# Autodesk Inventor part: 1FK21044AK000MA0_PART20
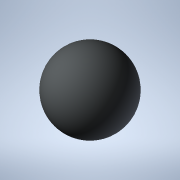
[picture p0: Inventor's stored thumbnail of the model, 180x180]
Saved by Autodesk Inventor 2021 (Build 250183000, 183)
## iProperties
Created: 2025-04
Part Number: 1FK21044AK000MA0_PART20
Material: Generic
Catalog Web Link: www.3dfindit.com
Description: -Servo synchronous motor
Document SubType Name: Modeling
Designer: psAdmin
Mass: 0.137258 g
Surface Area: 1.2868 cm^2
Volume: 0.137258 cm^3
Density: 1 g/cm^3
Appearance: PSOLRGB-212-217-219
Category: PARTsolutions
Title: 1FK21044AK000MA0_PART20
Author: Cadenas PARTsolutions
Comments: Servo synchronous motor
Sending System: PARTsolutions
Preprocessor: ST-DEVELOPER v19.3
PSOL_IDENT_0: {$CADENAS_DATA/23d-libs/siemens_ag/_cat_/87/f4/1fk21044ak000ma0.prj},216 {VTYP=3D},{NB=1FK21044AK000
PSOL_IDENT_1: MA0_PART20},{LINA=1FK21044AK000MA0_PART20},{NN=1FK21044AK000MA0_PART20},{NOPRJ=TRUE},{DATE=19.08.202
PSOL_IDENT_2: 5 14:00:48},{GEOMDATE=30.07.2025 02:00:50},{VERSION=},{LINEID=10},{WBVAR=},{WBNUMERIC=}  {NB=1FK2104
PSOL_IDENT_3: 4AK000MA0_PART20},{LINA=1FK21044AK000MA0_PART20},{KT=DUMMY},{PREVIEW=../../../_pool_/cb/72/p_d211_xx
PSOL_IDENT_4: _00434j.png},{DESCSHORT=SIMOTICS S-1FK2 HD, SINAMICS S210 3AC 400V-480V, 0.95 Nm, 6000 rpm},{DESCLON
PSOL_IDENT_5: G=SIMOTICS S-1FK2 HD servo motor M0=1.27 Nm; PN = 0.6 kW at nN=6000 rpm (380-480 V); PN = 0.4 kW at
PSOL_IDENT_6: nN=3000 rpm (200-240 V); degree of protection IP64; cylindrical shaft D19x40mm; absolute encoder 22-
PSOL_IDENT_7: bit + 12-bit multiturn (encoder AM22DQC); with OCC interface; plug size M17, rotatable; SIMOTICS S-1
PSOL_IDENT_8: FK2 servomotorfor a wide range of uses in industrial environments. SIMOTICS S‑1FK2 servomotors are c
PSOL_IDENT_9: ompact synchronous motors with a high dynamic performance that set themselves apart as a result of t
PSOL_IDENT_10: heir high power density, degree of protection and overload capability. The motors are available in t
PSOL_IDENT_11: wo variants: as High Dynamic variant (highest dynamic performance as a result of the low intrinsic m
PSOL_IDENT_12: oment of inertia for applications demanding a high dynamic performance with low moved masses) - and
PSOL_IDENT_13: as Compact variant (precise and stable closed-loop control for medium up to large moved masses as a
PSOL_IDENT_14: result of a medium intrinsic moment of inertia). SIMOTICSS‑1FK2 servomotors fully exploit their stre
PSOL_IDENT_15: ngths in a system with the SINAMICSS210 frequency converter and simple connection using the one cabl
PSOL_IDENT_16: e connection (OCC). Advantages include the short control and positioning times, fast and precise cor
PSOL_IDENT_17: rection of disturbing quantities as well as stable control with a high dynamic performance. The serv
PSOL_IDENT_18: o motors can be configured to address a wide range of requirements. For example with and without hol
PSOL_IDENT_19: ding brake, IP64 or IP65 degree of protection, singleturn or multiturn absolute encoders - to name j
PSOL_IDENT_20: ust a few. Further, the servomotors are available in different shaft heights extending from 20 to 10
PSOL_IDENT_21: 0. A shaft sealing ring is available to achieve an IP65 degree of protection and for subsequent moun
PSOL_IDENT_22: ting at the motor or as spare part. SIMOTICS - the optimum motor for each and every motion control a
PSOL_IDENT_23: pplication.},{INTNO=195125056312},{SUPPLIERALTNO=1FK2104-4AK00-0MA0},{MANUID=1FK21044AK000MA0},{MANU
PSOL_IDENT_24: NAME=Siemens},{MANUTYPEDESC=Synchronous motor 1FK2-HD 1,27 Nm},{AAU732=SIMOTICS},{AAO057=S-1FK2},{AA
PSOL_IDENT_25: U734=SIMOTICS S-1FK2 HD servo motor M0=1.27 Nm; PN = 0.6 kW at nN=6000 rpm (380-480 V); PN = 0.4 kW
PSOL_IDENT_26: at nN=3000 rpm (200-240 V); degree of protection IP64; cylindrical shaft D19x40mm; absolute encoder
PSOL_IDENT_27: 22-bit + 12-bit multiturn (encoder AM22DQC); with OCC interface; plug size M17, rotatable;},{AAW338=
PSOL_IDENT_28: Synchronous motor 1FK2-HD 1,27 Nm},{AAO742=SIMOTICS},{AAO663=4042948690994},{NOCUPEROU=1},{PRICEQUAN
PSOL_IDENT_29: TITY=1},{QUANTITYMIN=1},{QUANTITYINT=1},{CTN=85015100},{COO=DE},{AAO676=1FK2104-4AK00-0MA0},{AAO677=
PSOL_IDENT_30: Siemens AG},{ORDERUNIT=C62},{CONTENTUNIT=C62}
NB: 1FK21044AK000MA0_PART20
NT: Servo synchronous motor
NBSYN: $MANUID._PART20
LINA: 1FK21044AK000MA0_PART20
CATALOG: SIEMENS
PREVIEW: ../../../_pool_/cb/72/p_d211_xx_00434j.png
DESCSHORT: SIMOTICS S-1FK2 HD, SINAMICS S210 3AC 400V-480V, 0.95 Nm, 6000 rpm
DESCLONG: SIMOTICS S-1FK2 HD servo motor M0=1.27 Nm; PN = 0.6 kW at nN=6000 rpm (380-480 V); PN = 0.4 kW at nN=3000 rpm (200-240 V); degree of protection IP64; cylindrica
INTNO: 195125056312
SUPPLIERALTNO: 1FK2104-4AK00-0MA0
MANUID: 1FK21044AK000MA0
MANUNAME: Siemens
MANUTYPEDESC: Synchronous motor 1FK2-HD 1,27 Nm
AAU732: SIMOTICS
AAO057: S-1FK2
AAU734: SIMOTICS S-1FK2 HD servo motor M0=1.27 Nm; PN = 0.6 kW at nN=6000 rpm (380-480 V); PN = 0.4 kW at nN=3000 rpm (200-240 V); degree of protection IP64; cylindrica
AAW338: Synchronous motor 1FK2-HD 1,27 Nm
AAO742: SIMOTICS
AAO663: 4042948690994.0
NOCUPEROU: 1
PRICEQUANTITY: 1
QUANTITYMIN: 1
QUANTITYINT: 1
CTN: 85015100
COO: DE
ARTICLENO: 1FK21044AK000MA0_PART20
BOMINFO: 1FK21044AK000MA0_PART20
CREATOR: CADENAS GmbH
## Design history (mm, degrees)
feature "2025_04_17_15_37_40_0588"
body "Solid1"
